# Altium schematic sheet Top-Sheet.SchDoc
size Letter; Organization: Cegep Limoilou; Address1: 1300, 8e Avenue; Address2: Québec, QC; Address3: Canada; Address4: G1J 5L5; Revision: Enseignants; SheetNumber: 1; SheetTotal: 4; Conception: Ilyes Gharmoul; Titre: ADAM FRONT-DOOR SYST; Modification: Ilyes G
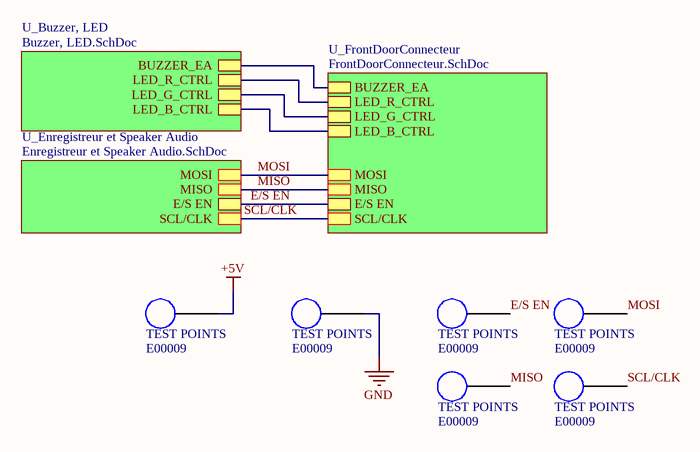
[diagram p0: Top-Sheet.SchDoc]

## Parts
T1  TEST POINTS  ADAM Inventory Number 1: E00009  [TEST POINTS]
T2  TEST POINTS  ADAM Inventory Number 1: E00009  [TEST POINTS]
T3  TEST POINTS  ADAM Inventory Number 1: E00009  [TEST POINTS]
T4  TEST POINTS  ADAM Inventory Number 1: E00009  [TEST POINTS]
T5  TEST POINTS  ADAM Inventory Number 1: E00009  [TEST POINTS]
T6  TEST POINTS  ADAM Inventory Number 1: E00009  [TEST POINTS]

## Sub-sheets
U_Buzzer, LED = Buzzer, LED.SchDoc: BUZZER_EA, LED_R_CTRL, LED_G_CTRL, LED_B_CTRL
U_Enregistreur et Speaker Audio = Enregistreur et Speaker Audio.SchDoc: MOSI, MISO, SCL/CLK, E/S EN
U_FrontDoorConnecteur = FrontDoorConnecteur.SchDoc: BUZZER_EA, LED_R_CTRL, LED_G_CTRL, LED_B_CTRL, MOSI, MISO, E/S EN, SCL/CLK

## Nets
+5V: T1.1
GND: T2.1
E/S EN: T3.1 ; sheet U_FrontDoorConnecteur/E/S EN, sheet U_Enregistreur et Speaker Audio/E/S EN
MISO: T5.1 ; sheet U_FrontDoorConnecteur/MISO, sheet U_Enregistreur et Speaker Audio/MISO
MOSI: T4.1 ; sheet U_FrontDoorConnecteur/MOSI, sheet U_Enregistreur et Speaker Audio/MOSI
SCL/CLK: T6.1 ; sheet U_FrontDoorConnecteur/SCL/CLK, sheet U_Enregistreur et Speaker Audio/SCL/CLK
(unnamed): sheet U_FrontDoorConnecteur/BUZZER_EA, sheet U_Buzzer, LED/BUZZER_EA
(unnamed): sheet U_FrontDoorConnecteur/LED_R_CTRL, sheet U_Buzzer, LED/LED_R_CTRL  [a separate net that carries the same name]
(unnamed): sheet U_FrontDoorConnecteur/LED_G_CTRL, sheet U_Buzzer, LED/LED_G_CTRL  [a separate net that carries the same name]
(unnamed): sheet U_FrontDoorConnecteur/LED_B_CTRL, sheet U_Buzzer, LED/LED_B_CTRL  [a separate net that carries the same name]

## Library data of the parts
T1-T6 = TEST POINTS: RCWCTE TEST POINTS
